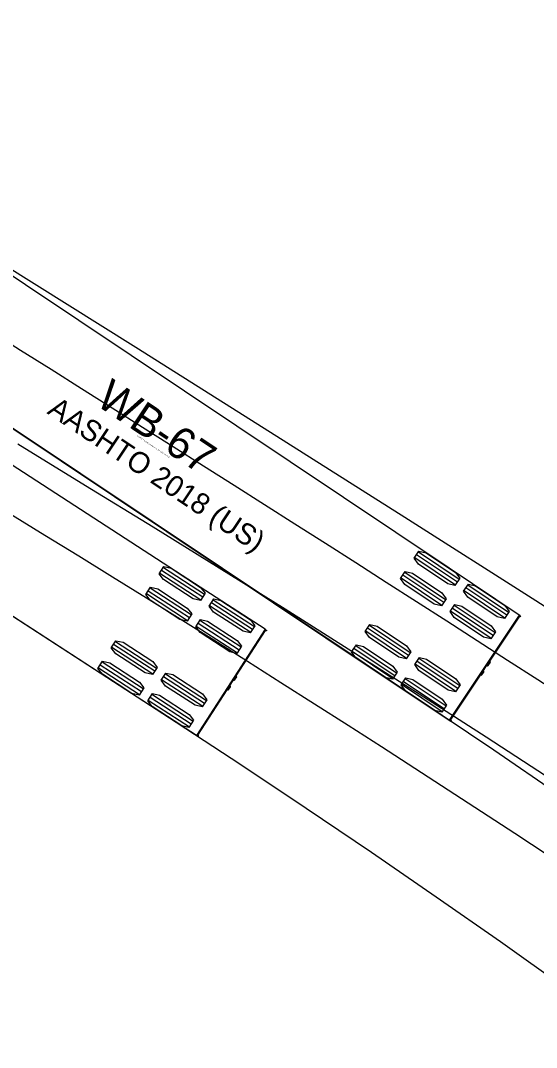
# Model space of a CAD drawing. Extents: x 973688 to 979179, y 703586 to 707602.
# Drawn here: x 978416.9 to 978451.7, y 704044.5 to 704113.5 of the extents above; entities that cross this region are included whole.
import ezdxf

# ---------------------------------------------------------------- set-up
doc = ezdxf.new("R2010")
doc.units = 0
doc.layers.add('Radius Check', color=7, linetype='Continuous')
doc.layers.add('T_Drafting', color=7, linetype='Continuous')

msp = doc.modelspace()

# ---------------------------------------------------------------- linework, layer by layer
at = {"layer": 'Radius Check'}
for p, q in [((978443.729, 704077.822), (978446.473, 704075.989)), ((978443.474, 704077.44), (978446.219, 704075.608)), ((978443.601, 704077.631), (978446.346, 704075.799)), ((978426.437, 704076.581), (978429.206, 704074.786)), ((978426.562, 704076.773), (978429.331, 704074.978)), ((978442.812, 704076.449), (978445.557, 704074.617)), ((978426.313, 704076.388), (978429.082, 704074.593)), ((978442.558, 704076.068), (978445.303, 704074.236)), ((978442.685, 704076.259), (978445.43, 704074.426)), ((978425.54, 704075.196), (978428.309, 704073.401)), ((978425.664, 704075.388), (978428.433, 704073.593)), ((978446.801, 704075.219), (978449.545, 704073.387)), ((978446.928, 704075.41), (978449.673, 704073.578)), ((978447.055, 704075.601), (978449.8, 704073.768)), ((978425.415, 704075.004), (978428.184, 704073.209)), ((978429.794, 704074.405), (978432.563, 704072.61)), ((978429.918, 704074.597), (978432.687, 704072.802)), ((978429.669, 704074.212), (978432.438, 704072.417)), ((978445.885, 704073.847), (978448.629, 704072.015)), ((978446.012, 704074.038), (978448.756, 704072.205)), ((978446.139, 704074.228), (978448.884, 704072.396)), ((978428.896, 704073.02), (978431.665, 704071.225)), ((978429.021, 704073.213), (978431.79, 704071.417)), ((978450.517, 704073.565), (978445.797, 704066.496)), ((978428.771, 704072.828), (978431.541, 704071.033)), ((978433.407, 704072.609), (978428.783, 704065.476)), ((978440.18, 704072.506), (978442.924, 704070.673)), ((978440.307, 704072.696), (978443.051, 704070.864)), ((978440.434, 704072.887), (978443.179, 704071.055)), ((978423.334, 704071.794), (978426.103, 704069.999)), ((978423.085, 704071.41), (978425.854, 704069.614)), ((978423.21, 704071.602), (978425.979, 704069.807)), ((978439.263, 704071.134), (978442.008, 704069.301)), ((978439.391, 704071.324), (978442.135, 704069.492)), ((978439.518, 704071.515), (978442.262, 704069.682)), ((978422.437, 704070.41), (978425.206, 704068.615)), ((978443.506, 704070.285), (978446.251, 704068.452)), ((978443.634, 704070.475), (978446.378, 704068.643)), ((978443.761, 704070.666), (978446.505, 704068.834)), ((978448.51, 704070.433), (978448.363, 704070.212)), ((978422.188, 704070.025), (978424.957, 704068.23)), ((978422.312, 704070.217), (978425.081, 704068.422)), ((978426.691, 704069.618), (978429.46, 704067.823)), ((978448.068, 704069.771), (978447.921, 704069.55)), ((978448.216, 704069.991), (978448.157, 704070.031)), ((978426.442, 704069.234), (978429.211, 704067.439)), ((978426.566, 704069.426), (978429.335, 704067.631)), ((978431.154, 704069.004), (978431.095, 704069.043)), ((978431.443, 704069.45), (978431.299, 704069.227)), ((978442.59, 704068.913), (978445.335, 704067.08)), ((978442.717, 704069.103), (978445.462, 704067.271)), ((978442.845, 704069.294), (978445.589, 704067.461)), ((978425.793, 704068.234), (978428.562, 704066.439)), ((978431.01, 704068.781), (978430.865, 704068.558)), ((978425.544, 704067.849), (978428.313, 704066.054)), ((978425.669, 704068.041), (978428.438, 704066.246))]:
    msp.add_line(p, q, dxfattribs=at)
for points in [[(978453.188, 704061.486), (978448.792, 704064.471), (978440.139, 704070.274), (978401.836, 704095.846), (978401.751, 704096.091), (978384.633, 704106.754), (978388.865, 704113.543), (978397.898, 704107.976), (978406.359, 704102.726), (978406.555, 704102.916), (978415.639, 704097.26), (978424.715, 704091.575), (978433.777, 704085.867), (978442.809, 704080.145), (978451.623, 704074.533), (978460.601, 704068.788)], [(978450.563, 704073.507), (978450.575, 704073.525), (978450.516, 704073.565), (978445.803, 704076.712), (978406.555, 704102.916), (978404.195, 704099.381), (978401.836, 704095.846), (978441.084, 704069.643), (978445.797, 704066.497), (978445.856, 704066.457), (978445.868, 704066.475)], [(978433.454, 704072.552), (978433.466, 704072.57), (978433.406, 704072.608), (978428.651, 704075.691), (978389.052, 704101.361), (978386.74, 704097.795), (978384.429, 704094.229), (978424.028, 704068.559), (978428.784, 704065.477), (978428.843, 704065.439), (978428.855, 704065.457)], [(978453.565, 704048.524), (978449.256, 704051.58), (978444.92, 704054.604), (978440.56, 704057.598), (978436.176, 704060.561), (978431.771, 704063.496), (978427.428, 704066.35), (978384.429, 704094.229)], [(978416.752, 704085.069), (978421.327, 704082.287), (978425.877, 704079.495), (978430.32, 704076.744), (978434.755, 704073.973), (978439.243, 704071.144), (978443.771, 704068.265), (978448.289, 704065.367), (978452.798, 704062.449)], [(978448.42, 704070.171), (978448.568, 704070.393), (978448.569, 704070.394), (978448.511, 704070.433), (978448.53, 704070.463), (978450.549, 704073.487), (978450.55, 704073.487)], [(978431.356, 704069.186), (978431.502, 704069.41), (978431.502, 704069.412), (978431.443, 704069.45), (978431.463, 704069.48), (978433.44, 704072.531), (978433.441, 704072.531)], [(978445.882, 704066.495), (978445.882, 704066.496), (978447.901, 704069.52), (978447.921, 704069.549), (978447.979, 704069.511), (978447.98, 704069.512), (978448.128, 704069.734)], [(978448.072, 704069.776), (978448.361, 704070.21)], [(978431.013, 704068.787), (978431.297, 704069.224)], [(978428.868, 704065.477), (978428.868, 704065.478), (978430.846, 704068.528), (978430.865, 704068.558), (978430.924, 704068.52), (978430.925, 704068.521), (978431.07, 704068.745)]]:
    msp.add_lwpolyline(points, dxfattribs=at)
for points in [[(978443.443, 704077.393), (978443.76, 704077.869), (978444.24, 704077.756), (978446.216, 704076.436), (978446.505, 704076.037), (978446.187, 704075.561), (978445.707, 704075.674), (978443.731, 704076.993)], [(978426.282, 704076.341), (978426.593, 704076.821), (978427.074, 704076.714), (978429.068, 704075.421), (978429.362, 704075.026), (978429.051, 704074.546), (978428.569, 704074.652), (978426.576, 704075.945)], [(978442.526, 704076.021), (978442.844, 704076.497), (978443.324, 704076.383), (978445.3, 704075.064), (978445.589, 704074.664), (978445.271, 704074.189), (978444.791, 704074.302), (978442.815, 704075.621)], [(978425.384, 704074.956), (978425.695, 704075.436), (978426.177, 704075.329), (978428.17, 704074.037), (978428.464, 704073.641), (978428.153, 704073.161), (978427.672, 704073.268), (978425.678, 704074.56)], [(978446.769, 704075.172), (978447.087, 704075.648), (978447.567, 704075.535), (978449.543, 704074.215), (978449.831, 704073.815), (978449.514, 704073.34), (978449.034, 704073.453), (978447.058, 704074.772)], [(978429.638, 704074.165), (978429.949, 704074.645), (978430.431, 704074.538), (978432.424, 704073.246), (978432.718, 704072.85), (978432.407, 704072.37), (978431.926, 704072.476), (978429.932, 704073.769)], [(978445.853, 704073.8), (978446.171, 704074.276), (978446.651, 704074.162), (978448.627, 704072.843), (978448.915, 704072.443), (978448.598, 704071.968), (978448.118, 704072.081), (978446.142, 704073.4)], [(978428.741, 704072.78), (978429.052, 704073.26), (978429.533, 704073.154), (978431.527, 704071.861), (978431.821, 704071.465), (978431.51, 704070.985), (978431.028, 704071.092), (978429.034, 704072.384)], [(978440.148, 704072.459), (978440.466, 704072.934), (978440.946, 704072.821), (978442.922, 704071.502), (978443.21, 704071.102), (978442.893, 704070.626), (978442.413, 704070.739), (978440.437, 704072.059)], [(978423.054, 704071.362), (978423.365, 704071.842), (978423.847, 704071.735), (978425.84, 704070.443), (978426.134, 704070.047), (978425.823, 704069.567), (978425.342, 704069.674), (978423.348, 704070.966)], [(978439.232, 704071.086), (978439.549, 704071.562), (978440.029, 704071.449), (978442.005, 704070.13), (978442.294, 704069.73), (978441.976, 704069.254), (978441.496, 704069.367), (978439.52, 704070.686)], [(978422.157, 704069.977), (978422.468, 704070.457), (978422.949, 704070.351), (978424.943, 704069.058), (978425.237, 704068.662), (978424.926, 704068.182), (978424.444, 704068.289), (978422.451, 704069.581)], [(978443.475, 704070.238), (978443.792, 704070.713), (978444.272, 704070.6), (978446.248, 704069.281), (978446.537, 704068.881), (978446.219, 704068.405), (978445.739, 704068.518), (978443.763, 704069.838)], [(978426.411, 704069.186), (978426.722, 704069.666), (978427.203, 704069.559), (978429.197, 704068.267), (978429.491, 704067.871), (978429.18, 704067.391), (978428.698, 704067.498), (978426.705, 704068.79)], [(978442.559, 704068.865), (978442.876, 704069.341), (978443.356, 704069.228), (978445.332, 704067.908), (978445.621, 704067.509), (978445.303, 704067.033), (978444.823, 704067.146), (978442.847, 704068.465)], [(978425.513, 704067.801), (978425.824, 704068.281), (978426.306, 704068.175), (978428.299, 704066.882), (978428.593, 704066.486), (978428.282, 704066.006), (978427.801, 704066.113), (978425.807, 704067.406)]]:
    msp.add_lwpolyline(points, close=True, dxfattribs=at)
for centre in [(978450.585, 704073.479), (978433.476, 704072.523), (978445.903, 704066.466), (978428.89, 704065.448)]:
    msp.add_circle(centre, 0.0266, dxfattribs=at)
for centre, radius, start, end in [((976519.884, 701071.256), 3566.494, 55.87597, 58.372335), ((977776.579, 703031.64), 1228.403, 52.999585, 60.987287), ((978452.244, 704072.385), 2.022, 146.27131, 146.95507), ((978435.15, 704071.452), 2.022, 147.04683, 147.73059), ((978448.391, 704070.191), 0.0354, 330.56285, 142.74831), ((978448.098, 704069.753), 0.0353, 149.60749, 327.95714), ((978448.099, 704069.753), 0.0352, 326.29658, 145.29699), ((978448.391, 704070.19), 0.0352, 147.24563, 326.24604), ((978431.327, 704069.206), 0.0352, 148.02115, 327.02156), ((978431.327, 704069.206), 0.0354, 331.33837, 143.52383), ((978431.04, 704068.764), 0.0353, 150.38301, 328.73266), ((978431.041, 704068.764), 0.0352, 327.0721, 146.07251), ((978445.903, 704066.466), 0.0363, 165.34876, 126.51011), ((978428.89, 704065.448), 0.0363, 166.12428, 127.28562)]:
    msp.add_arc(centre, radius, start, end, dxfattribs=at)
at = {"layer": 'T_Drafting'}
msp.add_arc((979663.259, 705993.334), 2322.185, 236.781575, 239.252706, dxfattribs=at)

# ---------------------------------------------------------------- texts
at = {"layer": 'Radius Check'}
for s, height, p in [('WB-67', 2.125, (978421.911, 704087.758)), ('AASHTO 2018 (US)', 1.41667, (978418.676, 704087.15)), ('(c) 2021 Transoft Solutions, Inc. All rights reserved.', 0.085, (978424.77, 704085.593))]:
    msp.add_text(s, height=height, rotation=326.27131, dxfattribs=at).set_placement(p)

doc.saveas('drawing.dxf')
